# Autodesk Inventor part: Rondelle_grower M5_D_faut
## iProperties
Created: 2011-10
Part Number: Rondelle_grower M5_D_faut
Document SubType Name: Modeling
Designer: Bruno
Author: Bruno
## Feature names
1. Base1
